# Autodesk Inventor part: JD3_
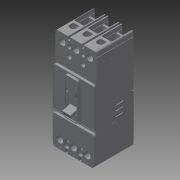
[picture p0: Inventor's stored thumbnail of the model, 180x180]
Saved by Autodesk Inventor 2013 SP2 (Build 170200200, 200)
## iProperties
Created: 2014-08
Part Number: JD3_
Material: Generic
Document SubType Name: Modeling
Designer: EM/EM
Density: 1 g/cm^3
Description: TYPE JD THERMAL MAGNETIC CIRCUIT BREAKERS THREE POLE, SERIES C
MXEDIT: false
MXINVTNRV: INV Versioned Component|JD3_|004.0
Author: EM/EM
Revision Number: 004
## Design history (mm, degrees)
derived "JD3_.iam"
node "L1"
node "L2"
node "L3"
node "T1"
node "T2"
node "T3"
sketch "Sketch1"
  geometry: C1 r 10.795 at (8.89, 11.913) reference; C2 r 10.795 at (8.89, 11.913); 1 further point
  constraints: 1 centre point, 1 coincident, 1 concentric
extrude "Extrusion1" cut sketch "Sketch1" distance "d1" = 9.525; taper "d2" = 0 deg
sketch "Sketch2"
  geometry: C1 r 6.35 at (0, 0) reference; C2 r 6.35 at (0, 0); 1 further point
  constraints: 1 centre point, 1 coincident, 1 concentric
extrude "Extrusion2" cut sketch "Sketch2" distance "d3" = 9.525; taper "d5" = 0 deg; dims "d4" = 4.7752, "d6" = 0
sketch "Sketch3"
  geometry: C1 r 10.795 at (11.494, 11.913) reference; C2 r 10.795 at (11.494, 11.913); 1 further point
  constraints: 1 centre point, 1 coincident, 1 concentric
extrude "Extrusion3" cut sketch "Sketch3" distance "d7" = 9.525; taper "d8" = 0 deg
sketch "Sketch4"
  geometry: C1 r 6.35 at (0, 0) reference; C2 r 6.35 at (0, 0); 1 further point
  constraints: 1 centre point, 1 coincident, 1 concentric
extrude "Extrusion4" cut sketch "Sketch4" distance "d9" = 9.525; taper "d11" = 0 deg; dims "d10" = 4.7752, "d12" = 0
sketch "Sketch5"
  geometry: C1 r 10.795 at (11.494, 11.913) reference; C2 r 10.795 at (11.494, 11.913); 1 further point
  constraints: 1 centre point, 1 coincident, 1 concentric
extrude "Extrusion5" cut sketch "Sketch5" distance "d13" = 9.525; taper "d14" = 0 deg
sketch "Sketch6"
  geometry: C1 r 6.35 at (0, 0) reference; C2 r 6.35 at (0, 0); 1 further point
  constraints: 1 centre point, 1 coincident, 1 concentric
extrude "Extrusion6" cut sketch "Sketch6" distance "d15" = 9.525; taper "d17" = 0 deg; dims "d16" = 4.7752, "d18" = 0
sketch "Sketch7"
  geometry: C1 r 8.738 at (-0.038, 0) reference; C2 r 8.738 at (-0.038, 0); 1 further point
  constraints: 1 centre point, 1 coincident, 1 concentric
extrude "Extrusion7" cut sketch "Sketch7" distance "d19" = 9.525; taper "d21" = 0 deg; dims "d20" = 4.7752, "d22" = 0
sketch "Sketch8"
  geometry: C1 r 8.738 at (-0.013, 0) reference; C2 r 8.738 at (-0.013, 0); 1 further point
  constraints: 1 centre point, 1 coincident, 1 concentric
extrude "Extrusion8" cut sketch "Sketch8" distance "d23" = 9.525; taper "d25" = 0 deg; dims "d24" = 4.7752, "d26" = 0
sketch "Sketch9"
  geometry: C1 r 8.738 at (0.013, 0) reference; C2 r 8.738 at (0.013, 0); 1 further point
  constraints: 1 centre point, 1 coincident, 1 concentric
extrude "Extrusion9" cut sketch "Sketch9" distance "d27" = 9.525; taper "d29" = 0 deg; dims "d28" = 4.7752, "d30" = 0
body "Solid1"
node "JD3_.ipt:1"
